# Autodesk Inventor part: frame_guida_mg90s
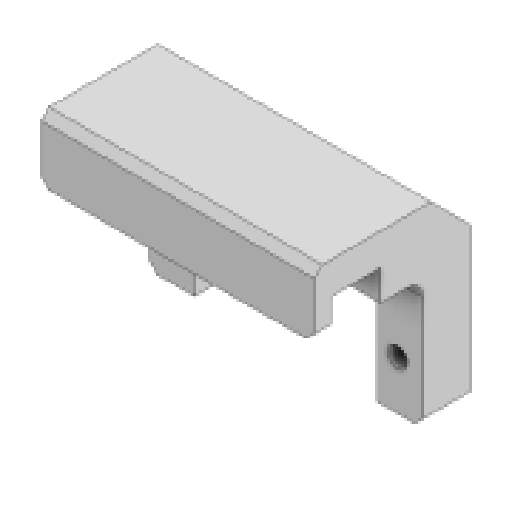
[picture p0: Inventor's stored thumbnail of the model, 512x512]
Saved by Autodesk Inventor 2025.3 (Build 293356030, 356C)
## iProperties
Created: 2026-04
Part Number: frame_guida_mg90s
Material: Generico
Document SubType Name: Modeling
Designer: R5800u
Density: 1 g/cm^3
Appearance: Default
Author: R5800u
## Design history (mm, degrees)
sketch "Schizzo1"
  geometry: L1 (1.475, 0.6)-(2.3, 0.6) reference; L2 (2.3, 0.6)-(2.3, 6.1) reference; L3 (-2.5, 6.1)-(2.3, 6.1) reference; L4 (-2.5, -6.1)-(-2.5, 6.1) reference; L5 (2.3, -6.1)-(-2.5, -6.1) reference; L6 (2.3, -6.1)-(2.3, -0.6) reference; L7 (2.3, -0.6)-(1.475, -0.6) reference; L8 (-29.075, -0.6)-(-29.9, -0.6) reference; L9 (-29.9, -0.6)-(-29.9, -6.1) reference; L10 (-25.1, -6.1)-(-29.9, -6.1) reference; L11 (-25.1, 0)-(-25.1, -6.1) reference; L12 (-25.1, 6.1)-(-25.1, 0) reference; L13 (-29.9, 6.1)-(-25.1, 6.1) reference; L14 (-29.9, 6.1)-(-29.9, 0.6) reference; L15 (-29.9, 0.6)-(-29.075, 0.6) reference; L16 (2.3, -6.1)-(-29.9, -6.1); L17 (-29.9, -6.1)-(-29.9, 17.9); L18 (-29.9, 17.9)-(2.3, 17.9); L19 (2.3, 17.9)-(2.3, -6.1); L20 (-2.3, 6.1)-(-2.3, -6.1) reference; L21 (-25.3, -6.1)-(-25.3, 6.1) reference; L22 (-2.3, 6.1)-(-2.3, 10.1); L23 (-2.3, 10.1)-(-25.3, 10.1); L24 (-25.3, 10.1)-(-25.3, 6.1); C1 r 1.25 at (0.1, 0); C2 r 1.25 at (-27.7, 0); A1 r 1.5 centre (0.1, 0) between (1.475, 0.6) and (1.475, -0.6) reference; A2 r 1.5 centre (-27.7, 0) between (-29.075, -0.6) and (-29.075, 0.6) reference; 7 further points
  constraints: 14 end point, 3 perpendicular, 2 centre point, 2 coincident, 2 parallel, 1 horizontal, 1 point on line
  dimensions: "d0" = 24 distance of L16.end L17.end; "d1" = 4 distance of L20.start L22.end; "d2" = 2.5 diameter of C1; "d3" = 2.5 diameter of C2
  node "Riferimento1"
  node "Riferimento2"
  node "Riferimento3"
  node "Riferimento4"
node "Piano di lavoro1"
extrude "Estrusione1" new body sketch "Schizzo1" distance "d4" = 6; taper "d5" = 0 deg
sketch "Schizzo2"
  geometry: L1 (-29.9, 17.9)-(-29.9, -6.1) reference; L2 (-29.9, -6.1)-(-25.3, -6.1) reference; L3 (-25.3, -6.1)-(-25.3, 10.1) reference; L4 (-25.3, 10.1)-(-2.3, 10.1) reference; L5 (-2.3, 10.1)-(-2.3, -6.1) reference; L6 (-2.3, -6.1)-(2.3, -6.1) reference; L7 (2.3, -6.1)-(2.3, 17.9) reference; L8 (2.3, 17.9)-(-29.9, 17.9) reference; L9 (-29.9, 17.9)-(2.3, 17.9); L10 (2.3, 17.9)-(2.3, 10.1); L11 (2.3, 10.1)-(-29.9, 10.1); L12 (-29.9, 10.1)-(-29.9, 17.9); C1 r 1.25 at (-27.7, 0) reference; C2 r 1.25 at (0.1, 0) reference; 4 further points
  constraints: 8 end point, 2 parallel, 1 horizontal, 1 perpendicular, 1 point on line
  node "Linea chiusa proiettata1"
node "Piano di lavoro2"
extrude "Estrusione2" join sketch "Schizzo2" distance "d6" = 5.3; taper "d7" = 0 deg
sketch "Schizzo3"
  geometry: L1 (0, 24)-(0, 0) reference; L2 (0, 0)-(6, 0) reference; L3 (6, 16.2)-(6, 0) reference; L4 (6, 16.2)-(11.3, 16.2) reference; L5 (0, 24)-(11.3, 24) reference; L6 (11.3, 24)-(11.3, 16.2) reference; 1 further point
extrude "Estrusione3" join sketch "Schizzo3" distance "d8" = 1; taper "d9" = 0 deg
sketch "Schizzo4"
  geometry: L1 (0, 0)-(0, 24) reference; L2 (0, 24)-(-11.3, 24) reference; L3 (-6, 16.2)-(-11.3, 16.2) reference; L4 (-6, 0)-(-6, 16.2) reference; L5 (0, 0)-(-6, 0) reference; L6 (-11.3, 16.2)-(-11.3, 24) reference; 1 further point
extrude "Estrusione4" join sketch "Schizzo4" distance "d10" = 1; taper "d11" = 0 deg
sketch "Schizzo7"
  geometry: L1 (3.3, 10.1)-(-30.9, 10.1) reference; L2 (3.3, 17.9)-(3.3, 10.1) reference; L3 (-30.9, 17.9)-(3.3, 17.9) reference; L4 (-30.9, 10.1)-(-30.9, 17.9) reference; L5 (2.5, 13.75)-(-43.5, 13.75) reference; L6 (3.3, 13.9)-(2.858, 13.9); L7 (2.858, 13.9)-(-30.9, 13.9); 1 further point
  constraints: 4 end point, 3 point on line, 1 perpendicular
  dimensions: "d18" = 0.15 distance from line of L7 L5.start
extrude "Estrusione7" join sketch "Schizzo7" distance "d19" = 6.3; taper "d20" = 0 deg
sketch "Schizzo8"
  geometry: L1 (-30.9, 17.9)-(-30.9, 13.9) reference; L2 (-30.9, 13.9)-(3.3, 13.9) reference; L3 (3.3, 13.9)-(3.3, 17.9) reference; L4 (3.3, 17.9)-(-30.9, 17.9) reference; L5 (3.3, -6.1)-(3.3, 17.9) reference; L6 (-30.9, 17.9)-(3.3, 17.9); L7 (3.3, 17.9)-(3.3, 9.9); L8 (3.3, 9.9)-(-30.9, 9.9); L9 (-30.9, 9.9)-(-30.9, 17.9); 2 further points
  constraints: 8 end point, 2 parallel, 1 horizontal, 1 perpendicular, 1 point on line
  dimensions: "d21" = 8 distance of L6.end L7.end
extrude "Estrusione8" join sketch "Schizzo8" distance "d22" = 2; taper "d23" = 0 deg
chamfer "Smusso1" distance "d24" = 5; stored, may be unused: second distance "d25" = 2, angle "d26" = 45 deg
chamfer "Smusso2" distance "d27" = 1; stored, may be unused: second distance "d28" = 2, angle "d29" = 45 deg
fillet "Raccordo1" dims "d30" = 2
node "Solido1"
node "Linea chiusa proiettata2"
node "Linea chiusa proiettata3"
node "Linea chiusa proiettata6"
node "Riferimento5"
node "Linea chiusa proiettata7"
